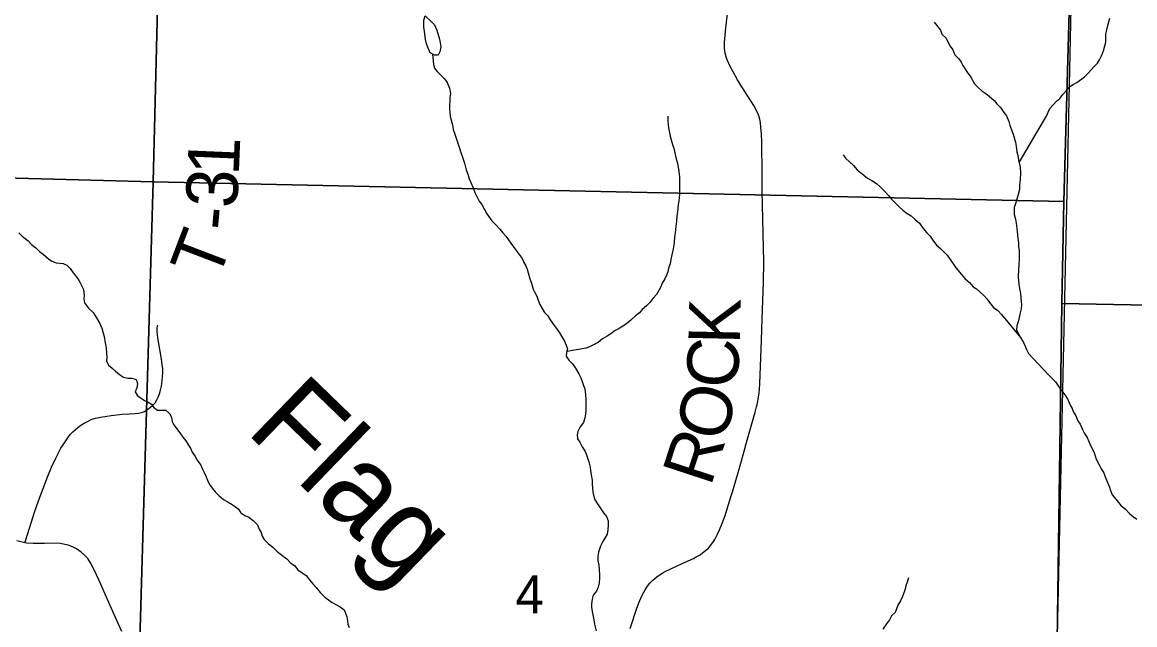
# Model space of a CAD drawing. Extents: x -7.9 to 76.1, y 0 to 22.
# Drawn here: x 4.221 to 5.448, y 15.904 to 16.568 of the extents above; entities that cross this region are included whole.
import ezdxf

# ---------------------------------------------------------------- set-up
doc = ezdxf.new("R2010")
doc.units = 0
for name, color, linetype in [('DV_X_Township_Line', 7, 'Continuous'), ('GM_X_Minor_River', 7, 'Continuous'), ('GM_X_Minor_River_Text', 7, 'Continuous'), ('GM_X_Section', 7, 'Continuous'), ('GM_X_Section_Text', 7, 'Continuous'), ('GM_X_State_Route', 7, 'Continuous'), ('GM_X_Township_Road', 7, 'Continuous'), ('GM_X_Township_Road_Text', 7, 'Continuous')]:
    doc.layers.add(name, color=color, linetype=linetype)

msp = doc.modelspace()

# ---------------------------------------------------------------- linework, layer by layer
at = {"layer": 'DV_X_Township_Line'}
msp.add_lwpolyline([(5.3187, 14.1), (5.3187, 14.1), (5.3308, 14.5457), (5.3468, 15.1527), (5.3492, 15.2488), (5.3496, 15.269), (5.3835, 16.8368), (5.4044, 17.6173), (5.4237, 18.2356), (4.9631, 18.2309), (4.7878, 18.2356), (4.712, 18.2376), (4.641, 18.2398), (3.9131, 18.2522), (2.8136, 18.2741), (2.7747, 18.2739), (2.7625, 18.2742), (2.7582, 18.2743), (2.1, 18.2862)], dxfattribs=at)
at = {"layer": 'GM_X_Minor_River'}
for points in [[(4.6656, 16.5749), (4.6718, 16.5693), (4.676, 16.5652), (4.6787, 16.5592), (4.6816, 16.5494), (4.6824, 16.5452), (4.6829, 16.5407), (4.6818, 16.5354), (4.68, 16.5315), (4.6758, 16.5315), (4.6712, 16.5344), (4.6693, 16.5386), (4.6673, 16.5442), (4.6661, 16.5491), (4.6651, 16.5582), (4.6643, 16.562), (4.6641, 16.5702), (4.6656, 16.5749)], [(5.2269, 16.5681), (5.2339, 16.5591), (5.2355, 16.5549), (5.2401, 16.5505), (5.242, 16.5463), (5.2448, 16.5414), (5.2475, 16.5377), (5.2499, 16.5321), (5.2541, 16.5276), (5.2568, 16.5238), (5.2588, 16.5201), (5.2634, 16.5129), (5.2673, 16.5073), (5.2716, 16.5002), (5.2755, 16.4961), (5.2797, 16.4924), (5.2839, 16.4894), (5.2877, 16.4864), (5.2931, 16.4816), (5.2962, 16.4779), (5.3001, 16.4741), (5.3039, 16.4685), (5.3067, 16.4648), (5.3094, 16.4584), (5.3106, 16.4542), (5.3122, 16.4493), (5.3142, 16.4444), (5.3158, 16.4395), (5.3166, 16.4357), (5.3175, 16.4312), (5.3183, 16.4251), (5.3192, 16.421), (5.32, 16.4161), (5.3212, 16.4115), (5.322, 16.4078), (5.3221, 16.4021), (5.3219, 16.3941), (5.3212, 16.3884), (5.321, 16.3835), (5.3192, 16.3766), (5.3177, 16.372), (5.3167, 16.3678), (5.3152, 16.3636), (5.3154, 16.3561), (5.3166, 16.3508), (5.3174, 16.3466), (5.3183, 16.3406), (5.3187, 16.3368), (5.3192, 16.33), (5.3201, 16.3247), (5.3202, 16.3205), (5.3206, 16.3163), (5.3208, 16.3072), (5.3205, 16.3004), (5.3202, 16.2951), (5.3196, 16.2871), (5.3205, 16.2792), (5.3213, 16.2746), (5.3222, 16.2689), (5.3227, 16.264), (5.3231, 16.2602), (5.3232, 16.2564), (5.3229, 16.2519), (5.3215, 16.2462), (5.3208, 16.2424), (5.3197, 16.2378), (5.3183, 16.2332), (5.318, 16.2287), (5.3223, 16.2204)], [(5.3318, 16.4322), (5.3514, 16.465), (5.3528, 16.4688), (5.3547, 16.473), (5.3584, 16.4768), (5.3618, 16.481), (5.3655, 16.4838), (5.3689, 16.4884), (5.373, 16.4926), (5.3767, 16.4972), (5.3805, 16.4992), (5.3842, 16.5015), (5.3929, 16.5077), (5.3974, 16.5123), (5.403, 16.5188), (5.4071, 16.5227), (5.4093, 16.5265), (5.4115, 16.5311), (5.4137, 16.5364), (5.4152, 16.5418), (5.4162, 16.546), (5.4165, 16.5543), (5.4176, 16.5597), (5.4186, 16.5642), (5.4208, 16.5726)], [(4.6739, 16.5327), (4.6749, 16.5212), (4.6761, 16.5174), (4.6788, 16.5137), (4.6834, 16.5092), (4.6869, 16.5055), (4.69, 16.5014), (4.6924, 16.4953), (4.6936, 16.4893), (4.6929, 16.4851), (4.6924, 16.4726), (4.6928, 16.4688), (4.6933, 16.4639), (4.6945, 16.4601), (4.6957, 16.4548), (4.6966, 16.4499), (4.6985, 16.4446), (4.6998, 16.4401), (4.7021, 16.4337), (4.7037, 16.4292), (4.705, 16.4242), (4.7069, 16.4193), (4.7089, 16.4126), (4.711, 16.4054), (4.7126, 16.4005), (4.7142, 16.3952), (4.7161, 16.3914), (4.7185, 16.3854), (4.7205, 16.3801), (4.7252, 16.3707), (4.7283, 16.367), (4.731, 16.3614), (4.7338, 16.3569), (4.7392, 16.349), (4.7434, 16.3449), (4.7481, 16.3397), (4.7515, 16.3359), (4.7546, 16.3322), (4.7577, 16.3281), (4.7601, 16.3243), (4.7651, 16.318), (4.7694, 16.312), (4.7725, 16.3075), (4.7744, 16.3033), (4.7768, 16.2996), (4.778, 16.2958), (4.7792, 16.2917), (4.7812, 16.2852), (4.7828, 16.2803), (4.7848, 16.2739), (4.7867, 16.2702), (4.7887, 16.266), (4.7903, 16.2615), (4.7923, 16.257), (4.7973, 16.248), (4.8008, 16.2442), (4.8035, 16.2401), (4.8074, 16.2349), (4.8113, 16.2293), (4.814, 16.2255), (4.8195, 16.2165), (4.8211, 16.212), (4.8226, 16.2078), (4.8216, 16.204), (4.8213, 16.1999), (4.824, 16.1954), (4.8282, 16.1913), (4.8313, 16.1868), (4.8352, 16.1804), (4.8372, 16.1759), (4.8388, 16.1721), (4.8404, 16.1676), (4.8416, 16.1638), (4.8424, 16.1578), (4.8429, 16.1517), (4.843, 16.1464), (4.8427, 16.1399), (4.8424, 16.1361), (4.8417, 16.132), (4.8403, 16.1266), (4.8366, 16.122), (4.8341, 16.117), (4.8334, 16.1132), (4.8338, 16.1087), (4.8362, 16.1049), (4.8389, 16.1), (4.842, 16.0948), (4.844, 16.0899), (4.846, 16.0835), (4.8476, 16.0775), (4.8481, 16.0737), (4.8489, 16.0691), (4.8498, 16.0631), (4.8498, 16.0593), (4.8507, 16.0498), (4.8524, 16.0423), (4.8571, 16.0348), (4.8625, 16.0273), (4.8656, 16.0232), (4.8676, 16.0183), (4.8676, 16.0141)], [(4.9332, 16.4643), (4.9333, 16.4597), (4.9337, 16.4552), (4.9342, 16.4514), (4.9358, 16.4423), (4.9371, 16.4382), (4.9386, 16.4333), (4.9399, 16.4291), (4.9407, 16.4253), (4.9423, 16.4189), (4.9439, 16.4121), (4.9452, 16.4061), (4.9461, 16.3974), (4.9463, 16.3856), (4.9461, 16.378), (4.9454, 16.3708), (4.9447, 16.367), (4.9441, 16.359), (4.9434, 16.3541), (4.9428, 16.3488), (4.9421, 16.3427), (4.9415, 16.3358), (4.9408, 16.3313), (4.9402, 16.3252), (4.9392, 16.318), (4.9378, 16.3115), (4.9367, 16.3066), (4.936, 16.3016), (4.9342, 16.297), (4.9332, 16.2928), (4.9317, 16.289), (4.9299, 16.2852), (4.927, 16.2802), (4.9251, 16.2756), (4.9207, 16.268), (4.9166, 16.2633), (4.9133, 16.2591), (4.9096, 16.2553), (4.9051, 16.2514), (4.9022, 16.2475), (4.8977, 16.2444), (4.8925, 16.2394), (4.8876, 16.2355), (4.8835, 16.2328), (4.8798, 16.2305), (4.8753, 16.2281), (4.8704, 16.2246), (4.8663, 16.2219), (4.8614, 16.2188), (4.8566, 16.2149), (4.8476, 16.2106), (4.8431, 16.2086), (4.8218, 16.2049)], [(5.3207, 16.4133), (5.3318, 16.4322)], [(5.1265, 16.4218), (5.1293, 16.418), (5.1381, 16.4102), (5.142, 16.4054), (5.1496, 16.3994), (5.1535, 16.3961), (5.1584, 16.3935), (5.1634, 16.3902), (5.1676, 16.3865), (5.1719, 16.382), (5.1765, 16.3768), (5.18, 16.373), (5.1842, 16.3689), (5.1881, 16.3648), (5.1923, 16.3607), (5.1973, 16.357), (5.2015, 16.3544), (5.2061, 16.3507), (5.2107, 16.3463), (5.215, 16.3406), (5.2189, 16.3358), (5.2227, 16.3321), (5.2254, 16.3279), (5.2297, 16.3223), (5.2339, 16.3186), (5.2378, 16.3149), (5.2412, 16.3111), (5.2447, 16.3066), (5.2471, 16.3029), (5.2502, 16.2984), (5.2533, 16.2947), (5.2571, 16.2898), (5.261, 16.2853), (5.266, 16.2812), (5.2698, 16.2767), (5.2737, 16.2742), (5.2775, 16.2708), (5.2817, 16.2667), (5.2852, 16.263), (5.2879, 16.2592), (5.2926, 16.2536), (5.2972, 16.2503), (5.3014, 16.2458), (5.3223, 16.2204)], [(4.2176, 16.3357), (4.2214, 16.3323), (4.228, 16.3271), (4.2315, 16.323), (4.2364, 16.3193), (4.2403, 16.3152), (4.2445, 16.3122), (4.2503, 16.307), (4.2541, 16.3045), (4.2587, 16.3026), (4.2666, 16.302), (4.2704, 16.3002), (4.2743, 16.2965), (4.2774, 16.2916), (4.2813, 16.2875), (4.284, 16.283), (4.2871, 16.277)], [(4.2871, 16.277), (4.2887, 16.2732), (4.2896, 16.2668), (4.2893, 16.263), (4.2901, 16.2588), (4.2944, 16.2528), (4.2994, 16.248), (4.3033, 16.242), (4.3068, 16.236), (4.3091, 16.2307), (4.312, 16.2201), (4.3124, 16.2163), (4.3137, 16.2092), (4.3141, 16.2031), (4.3146, 16.1989), (4.3143, 16.1948), (4.3163, 16.1899), (4.3205, 16.1865), (4.3243, 16.1832), (4.3286, 16.1798), (4.3331, 16.1769), (4.3377, 16.1758), (4.3423, 16.1755), (4.3468, 16.1741), (4.3484, 16.1696), (4.3477, 16.165), (4.3459, 16.1604), (4.3483, 16.1563), (4.3521, 16.1541), (4.3563, 16.1511), (4.3601, 16.1493), (4.3639, 16.1471), (4.3663, 16.1433), (4.3705, 16.1404), (4.3796, 16.1405), (4.3842, 16.1364), (4.3858, 16.1323), (4.3866, 16.1278), (4.3886, 16.124), (4.3913, 16.1203), (4.3951, 16.1154), (4.3983, 16.1105), (4.4017, 16.1064), (4.4041, 16.1027), (4.4068, 16.0985), (4.4088, 16.094), (4.4119, 16.0892), (4.4142, 16.0854), (4.4181, 16.0798), (4.4201, 16.0753), (4.422, 16.0715), (4.424, 16.067), (4.4256, 16.0632), (4.4279, 16.0583), (4.4306, 16.0542), (4.4341, 16.0505), (4.4384, 16.046), (4.4433, 16.0419), (4.4472, 16.0397), (4.451, 16.0375), (4.4552, 16.0349), (4.4594, 16.0316), (4.4625, 16.0271), (4.4667, 16.0241), (4.4713, 16.0223), (4.4759, 16.0186), (4.4809, 16.0138), (4.4825, 16.0092), (4.4849, 16.0055), (4.4861, 16.0013), (4.488, 15.9976), (4.493, 15.9931), (4.4976, 15.9894), (4.5022, 15.9849), (4.5076, 15.9805), (4.513, 15.9764), (4.5176, 15.9716), (4.5214, 15.969), (4.5253, 15.9645), (4.5299, 15.9612), (4.5345, 15.9582), (4.538, 15.9533), (4.5418, 15.9489), (4.5453, 15.9447), (4.55, 15.9395), (4.555, 15.9343), (4.5592, 15.9313), (4.563, 15.9284), (4.5672, 15.9262), (4.5718, 15.9236), (4.5764, 15.9203), (4.578, 15.9165), (4.5792, 15.9127), (4.58, 15.9082), (4.5805, 15.9044), (4.5817, 15.9006)], [(5.3223, 16.2204), (5.3254, 16.2148), (5.3274, 16.211), (5.329, 16.2072), (5.3309, 16.2027)], [(5.3309, 16.2027), (5.3526, 16.1795), (5.3572, 16.1754), (5.3607, 16.1716), (5.3645, 16.166), (5.368, 16.1615), (5.3711, 16.1573), (5.3746, 16.1521), (5.3769, 16.146), (5.3793, 16.1423), (5.3808, 16.1381), (5.3832, 16.134), (5.3855, 16.1287), (5.3882, 16.1249), (5.3906, 16.1189), (5.3929, 16.1147), (5.3956, 16.1102), (5.3976, 16.1057), (5.3999, 16.1008), (5.4034, 16.0936), (5.4058, 16.0864), (5.4089, 16.08), (5.4113, 16.0755), (5.414, 16.0714), (5.4156, 16.0668), (5.4203, 16.0555), (5.4215, 16.0517), (5.4234, 16.0472), (5.4273, 16.0423), (5.4334, 16.0348), (5.4377, 16.0315), (5.4423, 16.0266), (5.4469, 16.0229), (5.4507, 16.0202)], [(4.8676, 16.0141), (4.867, 16.0084), (4.8663, 16.0038), (4.8637, 15.9992), (4.8615, 15.9954), (4.859, 15.9904), (4.8568, 15.984), (4.8561, 15.9794), (4.8562, 15.9745), (4.8571, 15.9696), (4.8575, 15.9646), (4.858, 15.959), (4.8581, 15.9552), (4.8574, 15.9502), (4.8564, 15.9453), (4.8545, 15.9407), (4.8508, 15.9365), (4.8498, 15.9319), (4.8491, 15.9269), (4.8492, 15.9232), (4.85, 15.9186), (4.8509, 15.9129), (4.8517, 15.9092), (4.8525, 15.9043), (4.8542, 15.8971)], [(5.1986, 15.9554), (5.1972, 15.9509), (5.1958, 15.9467), (5.1947, 15.9421), (5.1922, 15.9349), (5.19, 15.9303), (5.187, 15.9253), (5.1842, 15.9173), (5.1801, 15.9138), (5.1779, 15.9092), (5.1745, 15.905), (5.1705, 15.8988)]]:
    msp.add_lwpolyline(points, dxfattribs=at)
at = {"layer": 'GM_X_Section'}
for points in [[(4.3909, 17.4116), (4.3656, 16.3922), (3.3491, 16.4191), (3.3681, 17.4339)], [(5.3971, 17.3953), (5.3953, 17.2709), (5.3702, 16.3705), (4.3656, 16.3922), (4.3909, 17.4116)], [(5.3953, 17.2709), (6.2529, 17.2478), (6.2227, 16.2415), (5.3678, 16.2579), (5.3702, 16.3705)], [(3.3491, 16.4191), (4.3656, 16.3922), (4.3363, 15.3822), (3.3274, 15.4069)], [(5.3702, 16.3705), (5.3678, 16.2579), (5.3554, 15.3537), (4.3363, 15.3822), (4.3656, 16.3922)], [(6.2227, 16.2415), (6.1958, 15.241), (5.3532, 15.2703), (5.3554, 15.3537), (5.3678, 16.2579)]]:
    msp.add_lwpolyline(points, close=True, dxfattribs=at)
at = {"layer": 'GM_X_State_Route'}
msp.add_lwpolyline([(4.3312, 15.8965), (4.3254, 15.9094), (4.3167, 15.9284), (4.3061, 15.9525), (4.3004, 15.9652), (4.2965, 15.9721), (4.2935, 15.9767), (4.2901, 15.9804), (4.2863, 15.984), (4.2839, 15.9857), (4.2812, 15.9874), (4.2788, 15.9887), (4.2743, 15.9907), (4.2718, 15.9915), (4.2684, 15.9924), (4.2637, 15.9932), (4.259, 15.9936), (4.2459, 15.9932), (4.2333, 15.9934), (4.2265, 15.9939), (4.2243, 15.9942), (4.2226, 15.9945), (4.2155, 15.9963)], dxfattribs=at)
at = {"layer": 'GM_X_Township_Road'}
for points in [[(4.8919, 15.8995), (4.8992, 15.9221), (4.9023, 15.9304), (4.9054, 15.9372), (4.9082, 15.9422), (4.911, 15.9464), (4.9136, 15.9495), (4.9167, 15.9528), (4.921, 15.9565), (4.9236, 15.9584), (4.9277, 15.961), (4.9303, 15.9624), (4.9484, 15.9708), (4.9559, 15.9741), (4.9617, 15.9768), (4.9647, 15.9785), (4.9688, 15.981), (4.9717, 15.983), (4.9748, 15.9855), (4.978, 15.9883), (4.9831, 15.9943), (4.9853, 15.9978), (4.9882, 16.0035), (4.9903, 16.0084), (4.9928, 16.0147), (4.996, 16.0232), (5.0032, 16.0459), (5.0046, 16.0505), (5.0126, 16.0777), (5.0174, 16.095), (5.0193, 16.1021), (5.0297, 16.1382), (5.0312, 16.1442), (5.0321, 16.148), (5.0329, 16.1526), (5.0339, 16.1595), (5.0343, 16.1634), (5.0347, 16.1692), (5.0365, 16.2174), (5.0372, 16.2412), (5.0387, 16.2816), (5.0391, 16.304), (5.0375, 16.3822), (5.0373, 16.4033), (5.0371, 16.4329), (5.037, 16.4363), (5.0366, 16.4446), (5.036, 16.4522), (5.0354, 16.457), (5.0346, 16.4612), (5.0332, 16.4659), (5.0312, 16.4708), (5.0283, 16.4762), (5.0148, 16.4966), (5.01, 16.5046), (5.0052, 16.5133), (5.0021, 16.5192), (4.9987, 16.5267), (4.9975, 16.5298), (4.9965, 16.5339), (4.9958, 16.5391), (4.9957, 16.543), (4.9957, 16.5456), (4.9974, 16.5617), (4.9991, 16.5774)], [(4.2243, 15.9942), (4.2297, 16.0113), (4.2349, 16.0278), (4.2393, 16.0404), (4.2496, 16.0676), (4.2537, 16.0775), (4.2582, 16.0873), (4.2623, 16.0955), (4.264, 16.0984), (4.2657, 16.101), (4.2723, 16.1109), (4.2745, 16.1139), (4.2771, 16.1165), (4.2796, 16.1188), (4.2823, 16.121), (4.285, 16.123), (4.2897, 16.1259), (4.294, 16.1284), (4.2981, 16.1303), (4.3022, 16.1317), (4.3075, 16.1328), (4.3194, 16.1346), (4.3316, 16.1358), (4.3395, 16.1362), (4.3459, 16.1365), (4.3494, 16.137), (4.3538, 16.1381), (4.3561, 16.1389), (4.3577, 16.1398), (4.36, 16.1413), (4.3646, 16.145), (4.3678, 16.1486), (4.3699, 16.1518), (4.3712, 16.1546), (4.3727, 16.1585), (4.3739, 16.1625), (4.3748, 16.1669), (4.3758, 16.1727), (4.3761, 16.177), (4.3763, 16.1814), (4.3762, 16.1862), (4.3758, 16.1898), (4.3753, 16.1942), (4.3709, 16.2202), (4.3704, 16.2236), (4.3701, 16.227), (4.3702, 16.2312), (4.3707, 16.2341)]]:
    msp.add_lwpolyline(points, dxfattribs=at)

# ---------------------------------------------------------------- texts
at = {"layer": 'GM_X_Minor_River_Text'}
msp.add_text('Flag', height=0.09471, rotation=315.9505, dxfattribs=at).set_placement((4.4666, 16.1169))
at = {"layer": 'GM_X_Section_Text'}
msp.add_text('4', height=0.0419, rotation=0, dxfattribs=at).set_placement((4.7652, 15.9165))
at = {"layer": 'GM_X_Township_Road_Text'}
for s, rotation, p in [('1', 87.6033, (4.4601, 16.3985)), ('3', 86.4073, (4.4578, 16.3622)), ('-', 84.7664, (4.4556, 16.3372)), ('T', 69.1345, (4.4366, 16.2811)), ('K', 88.7651, (5.0127, 16.2126)), ('C', 86.6923, (5.0099, 16.1637)), ('O', 76.0998, (4.9962, 16.1039)), ('R', 71.8082, (4.9804, 16.0551))]:
    msp.add_text(s, height=0.0568, rotation=rotation, dxfattribs=at).set_placement(p)

doc.saveas('drawing.dxf')
